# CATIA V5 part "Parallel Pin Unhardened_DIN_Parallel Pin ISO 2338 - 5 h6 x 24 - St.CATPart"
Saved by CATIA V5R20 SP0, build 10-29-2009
Part number: Parallel Pin Unhardened_DIN_Parallel Pin ISO 2338 - 5 h6 x 24 - St
Revision: ANY
Definition: UNKNOWN
Nomenclature: Parallel Pin Unhardened_DIN_Parallel Pin ISO 2338 - 5 h6 x 24 - St
Source: Unknown
Bounding box of the stored display mesh (mm): x 0 to 24, y -2.5 to 2.5, z -2.5 to 2.5
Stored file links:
  C:\Users\Utente\Desktop\IO LAVORO\3D X SITO CF\CUMSA\3D files SD\SD 3824\Parallel Pin Unhardened_DIN_Parallel Pin ISO 2338 - 5 h6 x 24 - St.CATPart
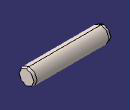
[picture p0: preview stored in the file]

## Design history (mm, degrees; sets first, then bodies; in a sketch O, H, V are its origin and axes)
Body1 "Base-Revolve" (main body)
  Solid1: solid without history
